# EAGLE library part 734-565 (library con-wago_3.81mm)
Serie 734, Federleiste mit abgewinkelten Einlötstiften / Series 734, Female connector with angled solder pins Polzahl / Pole No.: 5 Bemessungsspannung / Rated Voltage: 160 V Nennstrom / Nominal Current: 10 A Lötstiftlänge: / Solder Pin Length: 3.8 mm Farbe / Color: orange / orange Stand: 01.01.2012. Die jeweils aktuellen Daten zu diesem Artikel finden Sie in unserem Produktkatalog, den Sie unter www.wago.com einsehen können. As of: 01/01/2012. Please find the newest data for this article in our product catalogue, which can be viewed under www.wago.com.
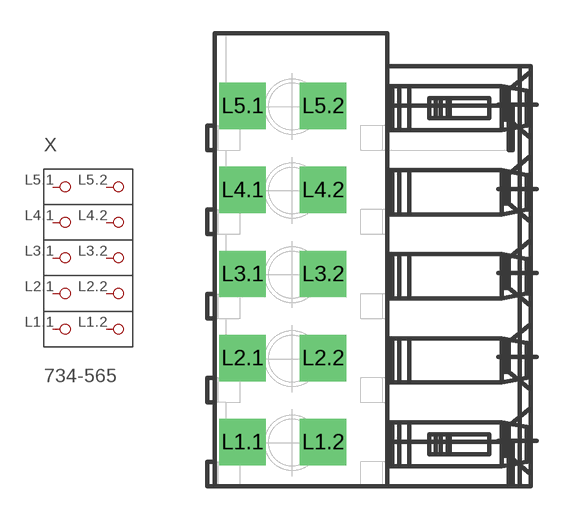
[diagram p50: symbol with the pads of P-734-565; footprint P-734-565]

Designator prefix X

## 734-565  [P-734-565]
L1.1  P1.1
L1.2  P1.2
L2.1  P2.1
L2.2  P2.2
L3.1  P3.1
L3.2  P3.2
L4.1  P4.1
L4.2  P4.2
L5.1  P5.1
L5.2  P5.2

## Footprint P-734-565 (pad centres in mm)
drill 1.4 square: L1.1 -5.86,-8.265; L1.2 -2.21,-8.265; L2.1 -5.86,-4.455; L2.2 -2.21,-4.455; L3.1 -5.86,-0.645; L3.2 -2.21,-0.645; L4.1 -5.86,3.165; L4.2 -2.21,3.165; L5.1 -5.86,6.975; L5.2 -2.21,6.975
